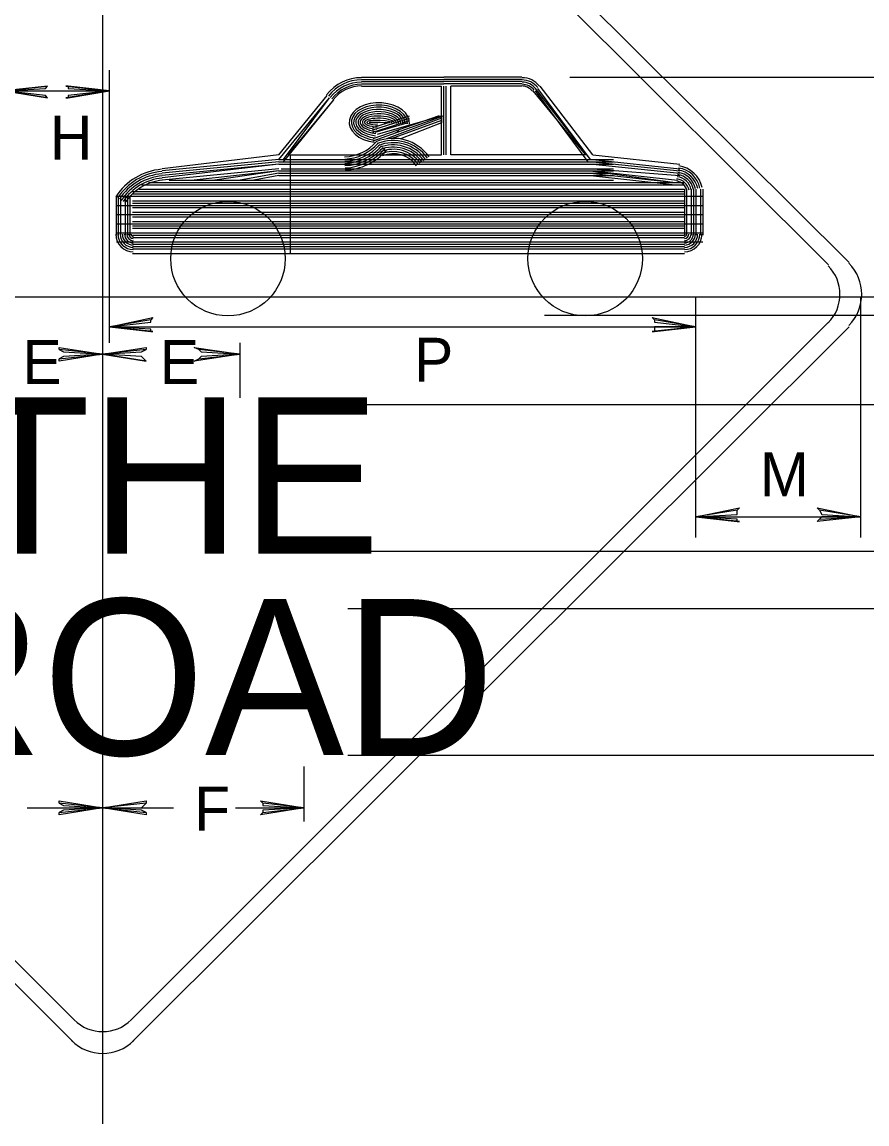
# Model space of a CAD drawing. Extents: x -0.018 to 0.195, y -0.006 to 0.263.
# Drawn here: x 0.0836 to 0.1297, y 0.1052 to 0.1654 of the extents above; entities that cross this region are included whole.
import ezdxf

# ---------------------------------------------------------------- set-up
doc = ezdxf.new("R2010")
doc.units = 0
doc.layers.add('1', color=7, linetype='Continuous')
doc.layers.add('12', color=7, linetype='Continuous')

msp = doc.modelspace()

# ---------------------------------------------------------------- linework, layer by layer
at = {"layer": '1'}
for p, q in [((0.088, 0.20175), (0.088, 0.10525)), ((0.1135, 0.162375), (0.1335, 0.162375)), ((0.032375, 0.150375), (0.143125, 0.150375)), ((0.129375, 0.13725), (0.129375, 0.150375)), ((0.112125, 0.149375), (0.154625, 0.149375)), ((0.097875, 0.1445), (0.14300000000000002, 0.1445)), ((0.120375, 0.138375), (0.129375, 0.138375)), ((0.097875, 0.1365), (0.14300000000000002, 0.1365)), ((0.101375, 0.133375), (0.14300000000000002, 0.133375)), ((0.101375, 0.12537500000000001), (0.14300000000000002, 0.12537500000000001))]:
    msp.add_line(p, q, dxfattribs=at)
msp.add_lwpolyline([(0.12712500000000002, 0.13875), (0.12725, 0.1385), (0.129375, 0.138375), (0.12712500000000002, 0.13875), (0.127, 0.138875), (0.129375, 0.138375), (0.12725, 0.138375), (0.12712500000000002, 0.13825), (0.129375, 0.138375), (0.127, 0.138125), (0.12712500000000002, 0.13825)], dxfattribs=at)
at = {"layer": '12'}
for p, q in [((0.089625, 0.19112500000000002), (0.12875, 0.15225)), ((0.0895, 0.19012500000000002), (0.12762500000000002, 0.152125)), ((0.088375, 0.147875), (0.088375, 0.16275)), ((0.10212500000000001, 0.162375), (0.106625, 0.162375)), ((0.110875, 0.162375), (0.106625, 0.162375)), ((0.10212500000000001, 0.16225), (0.106625, 0.16225)), ((0.10212500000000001, 0.162125), (0.106625, 0.162125)), ((0.10212500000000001, 0.162), (0.106625, 0.162)), ((0.10212500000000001, 0.161875), (0.1065, 0.161875)), ((0.1065, 0.15812500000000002), (0.1065, 0.161875)), ((0.110875, 0.16225), (0.106625, 0.16225)), ((0.110875, 0.162125), (0.106625, 0.162125)), ((0.110875, 0.162), (0.106625, 0.162)), ((0.106625, 0.15812500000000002), (0.106625, 0.161875)), ((0.10675, 0.15812500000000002), (0.10675, 0.161875)), ((0.10675, 0.15812500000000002), (0.10675, 0.161875)), ((0.110875, 0.161875), (0.107, 0.161875)), ((0.107, 0.15812500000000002), (0.107, 0.161875)), ((0.114625, 0.15787500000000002), (0.111625, 0.16175)), ((0.114625, 0.15787500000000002), (0.11175, 0.16175)), ((0.11475, 0.15812500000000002), (0.111875, 0.161875)), ((0.082625, 0.161625), (0.088375, 0.161625)), ((0.097625, 0.15812500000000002), (0.10025, 0.161375)), ((0.097625, 0.15787500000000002), (0.100375, 0.16125)), ((0.097875, 0.15787500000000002), (0.100375, 0.16125)), ((0.114375, 0.15812500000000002), (0.1115, 0.161625)), ((0.1145, 0.15775), (0.111625, 0.161625)), ((0.097875, 0.15775), (0.100625, 0.161125)), ((0.097875, 0.15775), (0.100625, 0.161125)), ((0.098125, 0.15812500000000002), (0.100625, 0.161125)), ((0.106625, 0.16025), (0.10275000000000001, 0.15887500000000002)), ((0.106375, 0.16025), (0.10275000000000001, 0.159)), ((0.10275000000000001, 0.15962500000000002), (0.10475, 0.16025)), ((0.10275000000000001, 0.1595), (0.10475, 0.160125)), ((0.10275000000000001, 0.15937500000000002), (0.10475, 0.16)), ((0.10300000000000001, 0.15925), (0.1065, 0.16025)), ((0.1065, 0.160125), (0.10350000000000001, 0.159)), ((0.1065, 0.16), (0.10375000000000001, 0.159)), ((0.1065, 0.16025), (0.1065, 0.15987500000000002)), ((0.10287500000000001, 0.15937500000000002), (0.104625, 0.15987500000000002)), ((0.1065, 0.15987500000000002), (0.10425, 0.159)), ((0.097625, 0.15812500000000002), (0.09125, 0.15737500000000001)), ((0.097625, 0.15787500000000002), (0.09125, 0.15725)), ((0.097625, 0.15775), (0.09125, 0.15712500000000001)), ((0.097625, 0.15762500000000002), (0.09125, 0.157)), ((0.097625, 0.15762500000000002), (0.09125, 0.15687500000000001)), ((0.097625, 0.15812500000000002), (0.097625, 0.15812500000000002)), ((0.097625, 0.15787500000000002), (0.115875, 0.15787500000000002)), ((0.097625, 0.15775), (0.115875, 0.15775)), ((0.097625, 0.15762500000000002), (0.115875, 0.15762500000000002)), ((0.097625, 0.15762500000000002), (0.115875, 0.15762500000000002)), ((0.098125, 0.15812500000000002), (0.1065, 0.15812500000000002)), ((0.09825, 0.15275), (0.09825, 0.15812500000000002)), ((0.114375, 0.15812500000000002), (0.107, 0.15812500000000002)), ((0.11475, 0.15812500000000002), (0.11475, 0.15812500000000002)), ((0.11475, 0.15812500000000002), (0.11950000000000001, 0.15762500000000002)), ((0.11475, 0.15787500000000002), (0.11950000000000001, 0.15737500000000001)), ((0.11475, 0.15775), (0.11950000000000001, 0.15725)), ((0.11475, 0.15762500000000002), (0.11950000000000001, 0.15712500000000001)), ((0.11475, 0.15762500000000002), (0.11950000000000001, 0.15712500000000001)), ((0.097625, 0.15737500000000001), (0.09125, 0.15675)), ((0.09175, 0.15737500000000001), (0.09175, 0.15737500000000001)), ((0.097625, 0.15725), (0.093, 0.15675)), ((0.097625, 0.15725), (0.094125, 0.15675)), ((0.097625, 0.15712500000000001), (0.0955, 0.15675)), ((0.097625, 0.157), (0.09625, 0.15675)), ((0.097625, 0.15725), (0.115875, 0.15725)), ((0.097625, 0.15712500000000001), (0.115875, 0.15712500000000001)), ((0.097625, 0.15712500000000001), (0.115875, 0.15712500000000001)), ((0.097625, 0.157), (0.115875, 0.157)), ((0.09775, 0.15737500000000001), (0.115875, 0.15737500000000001)), ((0.114625, 0.15725), (0.11925000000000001, 0.15662500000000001)), ((0.114625, 0.15712500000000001), (0.11925000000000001, 0.15662500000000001)), ((0.114625, 0.157), (0.11925000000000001, 0.1565)), ((0.11475, 0.15737500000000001), (0.11950000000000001, 0.157)), ((0.11475, 0.15725), (0.11937500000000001, 0.15675)), ((0.090125, 0.1565), (0.11975000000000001, 0.1565)), ((0.0905, 0.15662500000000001), (0.11975000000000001, 0.15662500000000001)), ((0.090875, 0.15662500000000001), (0.11975000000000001, 0.15662500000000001)), ((0.091625, 0.15675), (0.115875, 0.15675)), ((0.08875, 0.155875), (0.12075, 0.155875)), ((0.08875, 0.15375), (0.08875, 0.155875)), ((0.088875, 0.15375), (0.088875, 0.155875)), ((0.089, 0.15375), (0.089, 0.155875)), ((0.089, 0.15375), (0.089, 0.155875)), ((0.08925, 0.15375), (0.08925, 0.155875)), ((0.089375, 0.15375), (0.089375, 0.155875)), ((0.0895, 0.15375), (0.0895, 0.155875)), ((0.0895, 0.15375), (0.0895, 0.155875)), ((0.089625, 0.156125), (0.11975000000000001, 0.156125)), ((0.089625, 0.156125), (0.11975000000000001, 0.156125)), ((0.089625, 0.156), (0.11975000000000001, 0.156)), ((0.089625, 0.155875), (0.11975000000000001, 0.155875)), ((0.09, 0.15625), (0.11975000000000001, 0.15625)), ((0.11975000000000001, 0.15625), (0.11975000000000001, 0.15375)), ((0.11987500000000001, 0.15625), (0.11987500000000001, 0.15375)), ((0.11987500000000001, 0.15625), (0.11987500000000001, 0.15375)), ((0.120125, 0.15625), (0.120125, 0.15375)), ((0.12025, 0.15625), (0.12025, 0.15375)), ((0.120375, 0.15625), (0.120375, 0.15375)), ((0.120375, 0.15625), (0.120375, 0.15375)), ((0.120625, 0.15625), (0.120625, 0.15375)), ((0.12075, 0.15625), (0.12075, 0.15375)), ((0.08875, 0.155375), (0.12075, 0.155375)), ((0.089625, 0.155625), (0.11975000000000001, 0.155625)), ((0.089625, 0.155625), (0.11975000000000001, 0.155625)), ((0.089625, 0.1555), (0.11975000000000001, 0.1555)), ((0.089625, 0.155375), (0.11975000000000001, 0.155375)), ((0.089625, 0.15525), (0.11975000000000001, 0.15525)), ((0.089625, 0.15525), (0.11975000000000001, 0.15525)), ((0.08875, 0.154875), (0.12075, 0.154875)), ((0.089625, 0.155), (0.11975000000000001, 0.155)), ((0.089625, 0.154875), (0.11975000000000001, 0.154875)), ((0.089625, 0.15475), (0.11975000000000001, 0.15475)), ((0.089625, 0.15475), (0.11975000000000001, 0.15475)), ((0.08875, 0.154375), (0.12075, 0.154375)), ((0.089625, 0.1545), (0.11975000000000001, 0.1545)), ((0.089625, 0.154375), (0.11975000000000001, 0.154375)), ((0.089625, 0.15425), (0.11975000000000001, 0.15425)), ((0.089625, 0.15425), (0.11975000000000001, 0.15425)), ((0.089625, 0.154125), (0.11975000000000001, 0.154125)), ((0.08875, 0.153875), (0.12075, 0.153875)), ((0.08875, 0.153375), (0.12075, 0.153375)), ((0.089625, 0.153875), (0.11975000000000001, 0.153875)), ((0.089625, 0.15375), (0.11975000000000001, 0.15375)), ((0.089625, 0.15375), (0.11975000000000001, 0.15375)), ((0.089625, 0.153625), (0.11975000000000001, 0.153625)), ((0.089625, 0.153375), (0.11975000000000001, 0.153375)), ((0.089625, 0.15325), (0.11975000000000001, 0.15325)), ((0.089625, 0.15325), (0.11975000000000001, 0.15325)), ((0.089625, 0.153125), (0.11975000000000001, 0.153125)), ((0.089625, 0.153), (0.11975000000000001, 0.153)), ((0.089625, 0.15275), (0.11975000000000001, 0.15275)), ((0.089875, 0.15275), (0.11950000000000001, 0.15275)), ((0.09525, 0.15275), (0.09525, 0.15275)), ((0.120375, 0.13725), (0.120375, 0.150375)), ((0.08637500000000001, 0.10975), (0.04725, 0.14875)), ((0.08650000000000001, 0.110875), (0.048375, 0.149)), ((0.088375, 0.14875), (0.120375, 0.14875)), ((0.12762500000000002, 0.149), (0.0895, 0.110875)), ((0.12875, 0.14875), (0.089625, 0.10975)), ((0.0955, 0.144875), (0.0955, 0.147875)), ((0.099, 0.12175), (0.099, 0.12475)), ((0.083875, 0.1225), (0.088, 0.1225)), ((0.088, 0.1225), (0.091875, 0.1225)), ((0.09525, 0.1225), (0.099, 0.1225))]:
    msp.add_line(p, q, dxfattribs=at)
for points in [[(0.085, 0.16125), (0.084875, 0.161375), (0.082625, 0.161625), (0.085, 0.16125), (0.085, 0.16125), (0.082625, 0.161625), (0.084875, 0.16175), (0.085, 0.161875), (0.082625, 0.161625), (0.085, 0.161875), (0.085, 0.161875)], [(0.08612500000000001, 0.161875), (0.08612500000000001, 0.16175), (0.088375, 0.161625), (0.08612500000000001, 0.161875), (0.08600000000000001, 0.161875), (0.088375, 0.161625), (0.08612500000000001, 0.161375), (0.08612500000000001, 0.16125), (0.088375, 0.161625), (0.08600000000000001, 0.16125), (0.08612500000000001, 0.16125)], [(0.090625, 0.1485), (0.090625, 0.148625), (0.088375, 0.14875), (0.090625, 0.1485), (0.09075, 0.1485), (0.088375, 0.14875), (0.090625, 0.149), (0.090625, 0.149125), (0.088375, 0.14875), (0.09075, 0.14925), (0.090625, 0.149125)], [(0.11812500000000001, 0.149125), (0.11812500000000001, 0.149), (0.120375, 0.14875), (0.11812500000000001, 0.149125), (0.11800000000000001, 0.14925), (0.120375, 0.14875), (0.11812500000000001, 0.14875), (0.11812500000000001, 0.1485), (0.120375, 0.14875), (0.11800000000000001, 0.1485), (0.11812500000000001, 0.1485)], [(0.085625, 0.1475), (0.085875, 0.147375), (0.088, 0.14725), (0.085625, 0.1475), (0.085625, 0.147625), (0.088, 0.14725), (0.085875, 0.147125), (0.085625, 0.147), (0.088, 0.14725), (0.085625, 0.146875), (0.085625, 0.147)], [(0.090375, 0.146875), (0.090125, 0.147125), (0.088, 0.14725), (0.090375, 0.146875), (0.090375, 0.146875), (0.088, 0.14725), (0.090125, 0.147375), (0.090375, 0.1475), (0.088, 0.14725), (0.090375, 0.147625), (0.090375, 0.1475)], [(0.09325, 0.1475), (0.093375, 0.147375), (0.0955, 0.14725), (0.09325, 0.1475), (0.093, 0.147625), (0.0955, 0.14725), (0.093375, 0.147125), (0.09325, 0.147), (0.0955, 0.14725), (0.093, 0.146875), (0.09325, 0.147)], [(0.122625, 0.138125), (0.122625, 0.13825), (0.120375, 0.138375), (0.122625, 0.138125), (0.12275, 0.138125), (0.120375, 0.138375), (0.122625, 0.1385), (0.122625, 0.13875), (0.120375, 0.138375), (0.12275, 0.138875), (0.122625, 0.13875)], [(0.085625, 0.12275), (0.085875, 0.122625), (0.088, 0.1225), (0.085625, 0.12275), (0.085625, 0.122875), (0.088, 0.1225), (0.085875, 0.122375), (0.085625, 0.12225), (0.088, 0.1225), (0.085625, 0.122125), (0.085625, 0.12225)], [(0.090375, 0.12225), (0.090125, 0.122375), (0.088, 0.1225), (0.090375, 0.12225), (0.090375, 0.122125), (0.088, 0.1225), (0.090125, 0.1225), (0.090375, 0.12275), (0.088, 0.1225), (0.090375, 0.122875), (0.090375, 0.12275)], [(0.09675, 0.12275), (0.09675, 0.122625), (0.099, 0.1225), (0.09675, 0.12275), (0.096625, 0.122875), (0.099, 0.1225), (0.09675, 0.122375), (0.09675, 0.12225), (0.099, 0.1225), (0.096625, 0.122125), (0.09675, 0.12225)]]:
    msp.add_lwpolyline(points, dxfattribs=at)
for centre in [(0.09484172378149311, 0.15246679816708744), (0.1143389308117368, 0.15246679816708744)]:
    msp.add_circle(centre, 0.0031246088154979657, dxfattribs=at)
for centre, radius, start, end in [((0.10213117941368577, 0.15994154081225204), 0.0023998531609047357, 90, 142.46745), ((0.10213117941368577, 0.15994154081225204), 0.002279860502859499, 90, 142.46745), ((0.10213117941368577, 0.15994154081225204), 0.002159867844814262, 90, 142.46745), ((0.10213117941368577, 0.15994154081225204), 0.002039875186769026, 90, 142.46745), ((0.10213117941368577, 0.15994154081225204), 0.0019496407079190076, 90, 142.46745), ((0.11087577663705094, 0.1611634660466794), 0.0007278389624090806, 37.53137777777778, 90), ((0.1108901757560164, 0.1611414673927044), 0.0011999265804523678, 37.53137777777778, 90), ((0.1108901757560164, 0.1611414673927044), 0.001079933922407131, 37.53137777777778, 90), ((0.1108901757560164, 0.1611414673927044), 0.0009599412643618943, 37.53137777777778, 90), ((0.1108901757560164, 0.1611414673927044), 0.0008399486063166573, 37.53137777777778, 90), ((0.10110825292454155, 0.16046087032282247), 0.0024427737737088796, 272.29644444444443, 318.79271944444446), ((0.10110825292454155, 0.16046087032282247), 0.0025627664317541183, 272.29644444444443, 318.79271944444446), ((0.10386077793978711, 0.15662558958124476), 0.0024066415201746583, 35.41012500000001, 112.33950555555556), ((0.10386077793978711, 0.15662558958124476), 0.0022866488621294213, 35.41012500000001, 112.33950555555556), ((0.10386077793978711, 0.15662558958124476), 0.0021666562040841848, 35.41012500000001, 112.33950555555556), ((0.10110825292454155, 0.16046087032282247), 0.0026827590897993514, 272.29644444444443, 318.79271944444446), ((0.10110825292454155, 0.16046087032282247), 0.0028027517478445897, 272.29644444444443, 318.79271944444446), ((0.10110825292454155, 0.16046087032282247), 0.0029227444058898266, 272.29644444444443, 318.79271944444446), ((0.10110825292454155, 0.16046087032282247), 0.0030427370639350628, 272.29644444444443, 318.79271944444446), ((0.10110825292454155, 0.16046087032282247), 0.0031627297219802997, 272.29644444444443, 318.79271944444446), ((0.10386077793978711, 0.15662558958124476), 0.002046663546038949, 35.41012500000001, 112.33950555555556), ((0.10386077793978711, 0.15662558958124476), 0.0019266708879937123, 35.41012500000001, 112.33950555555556), ((0.10386077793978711, 0.15662558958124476), 0.0018066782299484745, 35.41012500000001, 112.33950555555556), ((0.10386077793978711, 0.15662558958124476), 0.0016866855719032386, 35.41012500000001, 112.33950555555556), ((0.10386077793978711, 0.15662558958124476), 0.0015666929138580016, 35.41012500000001, 112.33950555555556), ((0.09150475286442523, 0.15402919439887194), 0.003324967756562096, 94.96224444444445, 146.96526944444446), ((0.09150475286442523, 0.15402919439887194), 0.00320497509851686, 94.96224444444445, 146.96526944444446), ((0.09150475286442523, 0.15402919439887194), 0.003084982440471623, 94.96224444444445, 146.96526944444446), ((0.09150475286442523, 0.15402919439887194), 0.002964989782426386, 94.96224444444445, 146.96526944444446), ((0.11924212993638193, 0.15604118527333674), 0.0009016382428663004, 11.546911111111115, 82.31175555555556), ((0.11924212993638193, 0.15604118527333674), 0.0010216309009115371, 11.546911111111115, 82.31175555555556), ((0.11924212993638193, 0.15604118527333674), 0.0011416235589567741, 11.546911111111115, 82.31175555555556), ((0.11924212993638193, 0.15604118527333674), 0.001261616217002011, 11.546911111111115, 82.31175555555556), ((0.11924212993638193, 0.15604118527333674), 0.0013816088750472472, 11.546911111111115, 82.31175555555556), ((0.11924212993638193, 0.15604118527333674), 0.0015016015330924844, 11.546911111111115, 82.31175555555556), ((0.09150475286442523, 0.15402919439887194), 0.0028449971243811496, 94.96224444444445, 146.96526944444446), ((0.09150475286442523, 0.15402919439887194), 0.0027250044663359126, 94.96224444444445, 146.96526944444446), ((0.11924212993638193, 0.15604118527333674), 0.0006616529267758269, 11.546911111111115, 82.31175555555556), ((0.11924212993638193, 0.15604118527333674), 0.0007816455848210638, 11.546911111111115, 82.31175555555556), ((0.08967723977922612, 0.15380191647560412), 0.0009599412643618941, 180, 270), ((0.08967723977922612, 0.15380191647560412), 0.0008399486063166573, 180, 270), ((0.08967723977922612, 0.15380191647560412), 0.0007199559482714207, 180, 270), ((0.08967723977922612, 0.15380191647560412), 0.0005999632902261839, 180, 270), ((0.08967723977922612, 0.15380191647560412), 0.00047997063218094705, 180, 270), ((0.08967723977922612, 0.15380191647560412), 0.00035997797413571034, 180, 270), ((0.08967723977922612, 0.15380191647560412), 0.00023998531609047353, 180, 270), ((0.08967723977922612, 0.15380191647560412), 0.00011999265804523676, 180, 270), ((0.1197533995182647, 0.15380191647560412), 0.0009599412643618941, 270, 0), ((0.1197533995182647, 0.15380191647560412), 0.0008399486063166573, 270, 0), ((0.1197533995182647, 0.15380191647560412), 0.0007199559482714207, 270, 0), ((0.1197533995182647, 0.15380191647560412), 0.0005999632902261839, 270, 0), ((0.1197533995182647, 0.15380191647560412), 0.00047997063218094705, 270, 0), ((0.1197533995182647, 0.15380191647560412), 0.00035997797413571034, 270, 0), ((0.1197533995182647, 0.15380191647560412), 0.00023998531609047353, 270, 0), ((0.1197533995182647, 0.15380191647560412), 0.00011999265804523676, 270, 0), ((0.12703137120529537, 0.15052271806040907), 0.0023995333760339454, 315, 45), ((0.12604161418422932, 0.15052271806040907), 0.002199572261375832, 315, 45), ((0.08800665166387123, 0.11248775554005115), 0.002199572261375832, 225, 315), ((0.08800665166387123, 0.11149799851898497), 0.002399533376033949, 225.00000000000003, 315)]:
    msp.add_arc(centre, radius, start, end, dxfattribs=at)
for major_axis, ratio, start_param, end_param in [((-0.0016503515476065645, 4.884683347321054e-05), 0.6562755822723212, 3.1209935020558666, 7.708520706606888), ((-0.001530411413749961, 4.529686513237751e-05), 0.629337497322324, 3.1209935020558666, 7.708520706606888), ((-0.0014104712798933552, 4.174689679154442e-05), 0.5978180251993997, 3.1209935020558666, 7.708520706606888), ((-0.0012905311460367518, 3.81969284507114e-05), 0.5604398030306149, 3.1209935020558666, 7.708520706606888), ((-0.0011705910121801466, 3.464696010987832e-05), 0.5154019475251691, 3.1209935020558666, 7.708520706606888), ((-0.0010506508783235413, 3.109699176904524e-05), 0.46008123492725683, 3.1209935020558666, 7.708520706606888), ((-0.000930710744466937, 2.7547023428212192e-05), 0.3905022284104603, 3.1209935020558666, 7.708520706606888), ((-0.0008107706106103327, 2.399705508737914e-05), 0.300337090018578, 3.1209935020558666, 7.708520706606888), ((-0.0006908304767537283, 2.044708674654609e-05), 0.17886349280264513, 3.1209935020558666, 7.708520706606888), ((-0.0005708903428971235, 1.6897118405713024e-05), 0.0063483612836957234, 3.1209935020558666, 7.708520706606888), ((-0.0012905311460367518, 3.81969284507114e-05), 0.5604398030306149, 2.348331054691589, 2.5781574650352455)]:
    msp.add_ellipse((0.10310761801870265, 0.15988394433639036), major_axis=major_axis, ratio=ratio, start_param=start_param, end_param=end_param, dxfattribs=at)

# ---------------------------------------------------------------- texts
at = {"layer": '1'}
msp.add_text('M', height=0.00239925, dxfattribs=at).set_placement((0.123875, 0.1395))
at = {"layer": '12'}
for s, height, p in [('H', 0.00239925, (0.085125, 0.15787500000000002)), ('E', 0.00239925, (0.083625, 0.145625)), ('E', 0.00239925, (0.091125, 0.145625)), ('P', 0.00239925, (0.105, 0.14575)), ('THE', 0.008517, (0.080375, 0.136375)), ('ROAD', 0.008517, (0.0765, 0.12537500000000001)), ('F', 0.00239925, (0.093, 0.12125))]:
    msp.add_text(s, height=height, dxfattribs=at).set_placement(p)

doc.saveas('drawing.dxf')
